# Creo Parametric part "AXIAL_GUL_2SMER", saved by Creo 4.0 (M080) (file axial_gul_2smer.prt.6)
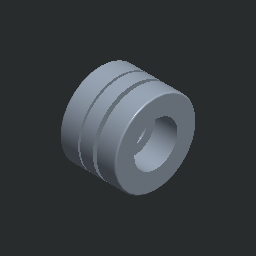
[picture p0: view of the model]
Units: millimeter Kilogram Sec (mmKs); MM, KILOGRAM, SECS
Materials in the file: OCEL_N

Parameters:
  MFG_WP_MATERIAL = "RO6_5"
  NAZOV = "AXIAL_GUL_2SMER"
  PTC_MATERIAL_NAME = "OCEL_N"

Other parameters: HMOTNOST, HUSTOTA, D16, D17, D20

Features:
  1. round
  2. round

Layers: 1, 2, 3, 4, 5, 6, 7, 8, 9, 10, 11, 12, 13, 14, 15, 16, 17, 18, 19, 20, 21, 22, 23, 24, 25, 26, 27, 28, 29, 30, 31, 32

Family table entries: GENERIC, LOZISKO_52202A, AXIAL_GUL_2SMER, value(d_val), 2/@, 2/@, 2/1, 2/6, value(i_val), LOZISKO_52204A, AXIAL_GUL_2SMER, !/., 2/D, 2/D, 2/6, 2/:, LOZISKO_52405A, AXIAL_GUL_2SMER, !/., 2/N, 2/N, 2/;, 2/&, LOZISKO_52205A, AXIAL_GUL_2SMER, !/4, 2/;, 2/<, LOZISKO_52305A, AXIAL_GUL_2SMER, !/4, 2/J, 2/J, 2/;, 2/A, 2/ , LOZISKO_52406A, AXIAL_GUL_2SMER, !/4, 2/@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

Surfaces: 16 cylinder, 8 plane, 8 torus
